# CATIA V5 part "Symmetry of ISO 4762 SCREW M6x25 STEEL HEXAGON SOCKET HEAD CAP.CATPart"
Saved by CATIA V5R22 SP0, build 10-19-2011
Part number: Symmetry of ISO 4762 SCREW M6x25 STEEL HEXAGON SOCKET HEAD CAP
Bounding box of the stored display mesh (mm): x -25 to 6, y -5 to 5, z -4.99 to 4.99
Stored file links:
  D:\CAO_PER_MODIF_2025\CAO_PER_pick&place_2024P\Symmetry of ISO 4762 SCREW M6x25 STEEL HEXAGON SOCKET HEAD CAP.CATPart
  D:\CAO_PER_MODIF_2025\CAO_PER_pick&place_2024P\ISO_4762_M6x25_STEEL_HEXAGON_SOCKET_HEAD_CAP_SCREW.CATPart
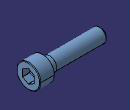
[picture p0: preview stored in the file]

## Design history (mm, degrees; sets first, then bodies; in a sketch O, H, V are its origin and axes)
Body1 (main body)
  Body2 "Corps du corps principal d'origine"
    Solid1: linked copy from another document
  Assemble1: tool Body2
